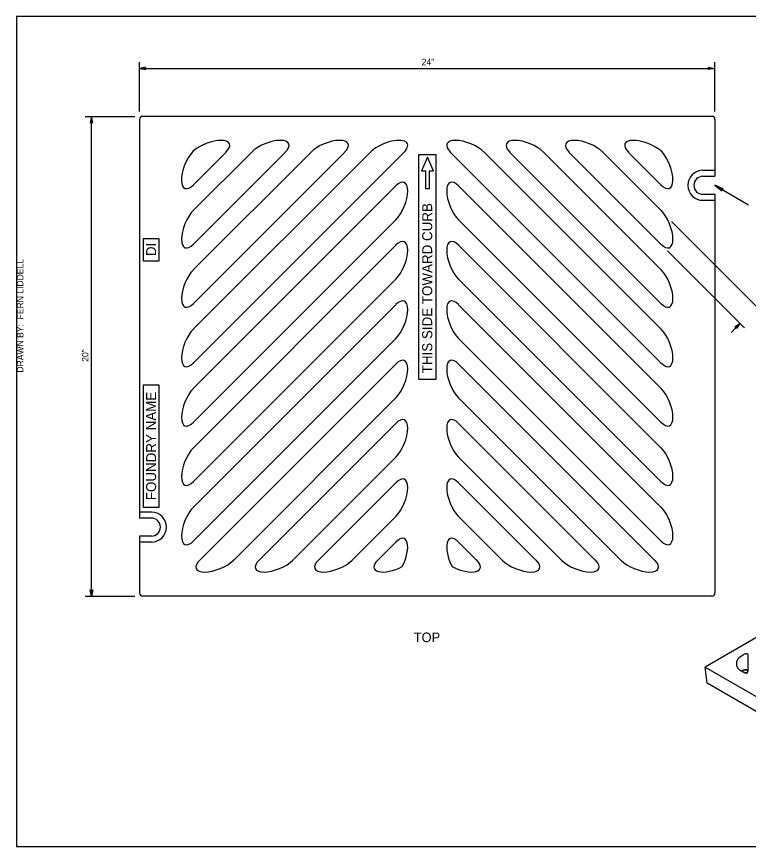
# Model space of a CAD drawing. Extents: x 99862 to 103151, y 100000 to 102076.
# Drawn here: x 99862 to 101693, y 100000 to 102076 of the extents above; entities that cross this region are included whole.
import ezdxf

# ---------------------------------------------------------------- set-up
doc = ezdxf.new("R2010")
doc.units = 0
for name, color, linetype in [('Level 1', 7, 'Continuous'), ('Level 11', 7, 'Continuous'), ('Level 15', 7, 'Continuous'), ('Level 2', 7, 'Continuous'), ('Level 20', 7, 'Continuous'), ('Level 6', 7, 'Continuous'), ('Level 60', 7, 'Continuous'), ('Level 62', 7, 'Continuous')]:
    doc.layers.add(name, color=color, linetype=linetype)

msp = doc.modelspace()

# ---------------------------------------------------------------- linework, layer by layer
at = {"layer": 'Level 1'}
msp.add_lwpolyline([(99862, 99999.5), (103151, 99999.5), (103151, 102075.5), (99862, 102075.5)], close=True, dxfattribs=at)
at = {"layer": 'Level 11'}
for p, q in [((101579.6, 101690.9), (101609.6, 101690.9)), ((101579.6, 101675.9), (101609.6, 101675.9)), ((101579.6, 101630.9), (101609.6, 101630.9)), ((101579.6, 101615.9), (101609.6, 101615.9)), ((100199.6, 100835.9), (100169.6, 100835.9)), ((100199.6, 100820.9), (100169.6, 100820.9)), ((100199.6, 100775.9), (100169.6, 100775.9)), ((100199.6, 100760.9), (100169.6, 100760.9))]:
    msp.add_line(p, q, dxfattribs=at)
for points in [[(100868.3, 101730.7), (100910.9, 101730.7), (100910.9, 101167.3), (100868.3, 101167.3)], [(100178.4, 101464.3), (100218.9, 101464.3), (100218.9, 101519.9), (100178.4, 101519.9)], [(100178.4, 100848.6), (100218.9, 100848.6), (100218.9, 101153.1), (100178.4, 101153.1)]]:
    msp.add_lwpolyline(points, close=True, dxfattribs=at)
msp.add_lwpolyline([(100875.6, 101689.4), (100885.4, 101689.4), (100885.4, 101645.1), (100895.3, 101645.1), (100895.3, 101689.4), (100905.1, 101689.4), (100890.3, 101723.8), (100875.6, 101689.4)], dxfattribs=at)
for centre, radius, start, end in [((101579.6, 101653.4), 37.5, 90, 270), ((101579.6, 101653.4), 22.5, 90, 270), ((100199.6, 100798.4), 37.5, 270, 90), ((100199.6, 100798.4), 22.5, 270, 90)]:
    msp.add_arc(centre, radius, start, end, dxfattribs=at)
at = {"layer": 'Level 15'}
for p, q in [((100169.6, 101837.9), (100169.6, 101961.9)), ((101609.6, 101837.9), (101609.6, 101961.9)), ((100169.6, 101945.9), (101609.6, 101945.9)), ((100033.6, 101825.9), (100157.6, 101825.9)), ((100049.6, 100625.9), (100049.6, 101825.9)), ((101609.1, 101653.5), (101693.4, 101604.8)), ((101501.3, 101563.1), (101725.7, 101338.7)), ((101491.2, 101489.5), (101683.9, 101296.8)), ((101650, 101285.5), (101672.6, 101308.2)), ((100033.6, 100625.9), (100157.6, 100625.9))]:
    msp.add_line(p, q, dxfattribs=at)
for points in [[(100169.6, 101945.9), (100185.3, 101942.8), (100184.6, 101945.9), (100185.3, 101949)], [(101609.6, 101945.9), (101593.9, 101942.8), (101594.6, 101945.9), (101593.9, 101949)], [(100049.6, 101825.9), (100046.5, 101810.2), (100049.6, 101810.9), (100052.7, 101810.2)], [(101609.1, 101653.5), (101627.3, 101639.5), (101627.9, 101642.6), (101630.3, 101644.7)], [(101672.6, 101308.2), (101663.7, 101294.9), (101662, 101297.6), (101659.3, 101299.2)], [(100049.6, 100625.9), (100046.5, 100641.6), (100049.6, 100640.9), (100052.7, 100641.6)]]:
    msp.add_lwpolyline(points, close=True, dxfattribs=at)
at = {"layer": 'Level 2'}
for p, q in [((100169.6, 101818.1), (100169.6, 100820.9)), ((101601.8, 101825.9), (100177.4, 101825.9)), ((101609.6, 101818.1), (101609.6, 101675.9)), ((101609.6, 101630.9), (101609.6, 100633.7)), ((100169.6, 100775.9), (100169.6, 100633.7)), ((101601.8, 100625.9), (100177.4, 100625.9)), ((101584.8, 100448.1), (102009.1, 100203.1))]:
    msp.add_line(p, q, dxfattribs=at)
for points in [[(100304.4, 101590.8), (100304.6, 101591), (100449.5, 101735.9), (100449.5, 101735.9)], [(100304.4, 101442.3), (100304.6, 101442.5), (100598, 101735.9), (100598, 101735.9)], [(100304.4, 101293.9), (100304.6, 101294), (100746.5, 101735.9), (100746.5, 101735.9)], [(100386, 101736), (100385.8, 101735.9), (100304.6, 101654.6), (100304.6, 101654.6)], [(100534.5, 101736), (100534.3, 101735.9), (100304.6, 101506.2), (100304.6, 101506.2)], [(100683, 101736), (100682.8, 101735.9), (100304.6, 101357.7), (100304.6, 101357.7)], [(100831.3, 101735.9), (100831.3, 101735.9), (100304.6, 101209.2), (100304.6, 101209.2)], [(100947.9, 101735.9), (100947.9, 101735.9), (101474.6, 101209.2), (101474.6, 101209.2)], [(101474.8, 101293.9), (101474.6, 101294), (101032.7, 101735.9), (101032.7, 101735.9)], [(101096.2, 101736), (101096.4, 101735.9), (101474.6, 101357.7), (101474.6, 101357.7)], [(101474.8, 101442.3), (101474.6, 101442.5), (101181.2, 101735.9), (101181.2, 101735.9)], [(101244.7, 101736), (101244.9, 101735.9), (101474.6, 101506.2), (101474.6, 101506.2)], [(101474.8, 101590.8), (101474.6, 101591), (101329.7, 101735.9), (101329.7, 101735.9)], [(101393.2, 101736), (101393.4, 101735.9), (101474.6, 101654.6), (101474.6, 101654.6)], [(100304.4, 101145.4), (100304.6, 101145.5), (100810.8, 101651.8), (100810.8, 101651.8)], [(101474.8, 101145.4), (101474.6, 101145.5), (100968.3, 101651.8), (100968.3, 101651.8)], [(100811, 101567.1), (100810.8, 101566.9), (100304.6, 101060.7), (100304.6, 101060.7)], [(100968.2, 101567.1), (100968.3, 101566.9), (101474.6, 101060.7), (101474.6, 101060.7)], [(100304.4, 100996.9), (100304.6, 100997), (100810.8, 101503.3), (100810.8, 101503.3)], [(101474.8, 100996.9), (101474.6, 100997), (100968.3, 101503.3), (100968.3, 101503.3)], [(100811, 101418.6), (100810.8, 101418.4), (100304.6, 100912.2), (100304.6, 100912.2)], [(100968.2, 101418.6), (100968.3, 101418.4), (101474.6, 100912.2), (101474.6, 100912.2)], [(100304.4, 100848.4), (100304.6, 100848.6), (100810.8, 101354.8), (100810.8, 101354.8)], [(101474.8, 100848.4), (101474.6, 100848.6), (100968.3, 101354.8), (100968.3, 101354.8)], [(100811, 101270.1), (100810.8, 101269.9), (100304.6, 100763.7), (100304.6, 100763.7)], [(100968.2, 101270.1), (100968.3, 101269.9), (101474.6, 100763.7), (101474.6, 100763.7)], [(100320.2, 100715.7), (100320.4, 100715.9), (100810.8, 101206.3), (100810.8, 101206.3)], [(101459, 100715.7), (101458.8, 100715.9), (100968.3, 101206.3), (100968.3, 101206.3)], [(100811, 101121.6), (100810.8, 101121.4), (100405.3, 100715.9), (100405.2, 100715.9)], [(100968.2, 101121.6), (100968.3, 101121.4), (101373.9, 100715.9), (101373.9, 100715.9)], [(100468.7, 100715.7), (100468.9, 100715.9), (100810.8, 101057.8), (100810.8, 101057.8)], [(101310.5, 100715.7), (101310.3, 100715.9), (100968.3, 101057.8), (100968.3, 101057.8)], [(100811, 100973.1), (100810.8, 100973), (100553.7, 100715.9), (100553.7, 100715.9)], [(100968.2, 100973.1), (100968.3, 100973), (101225.4, 100715.9), (101225.4, 100715.9)], [(100617.2, 100715.7), (100617.4, 100715.9), (100810.8, 100909.3), (100810.8, 100909.3)], [(101162, 100715.7), (101161.8, 100715.9), (100968.3, 100909.3), (100968.3, 100909.3)], [(100811, 100824.6), (100810.8, 100824.5), (100702.2, 100715.9), (100702.2, 100715.9)], [(100968.2, 100824.6), (100968.3, 100824.5), (101077, 100715.9), (101077, 100715.9)], [(100765.7, 100715.7), (100765.9, 100715.9), (100810.8, 100760.8), (100810.8, 100760.8)], [(101013.5, 100715.7), (101013.3, 100715.9), (100968.3, 100760.8), (100968.3, 100760.8)]]:
    msp.add_lwpolyline(points, dxfattribs=at)
for centre, start, end in [((100177.4, 101818.1), 90, 180), ((101601.8, 101818.1), 0, 90), ((100177.4, 100633.7), 180, 270), ((101601.8, 100633.7), 270, 0)]:
    msp.add_arc(centre, 7.82, start, end, dxfattribs=at)
for centre, major_axis, start_param, end_param in [((100343.4, 101735.9), (51.2, 21.2), 5.503483, 8.580913), ((100491.9, 101735.9), (51.2, 21.2), 5.503483, 8.63938), ((100640.4, 101735.9), (51.2, 21.2), 5.503483, 8.63938), ((100788.9, 101735.9), (51.2, 21.2), 5.497787, 8.63938), ((100990.3, 101735.9), (-51.2, 21.2), 3.926991, 7.068583), ((101138.8, 101735.9), (-51.2, 21.2), 3.926991, 7.062888), ((101287.3, 101735.9), (-51.2, 21.2), 3.926991, 7.062888), ((101435.8, 101735.9), (-51.2, 21.2), 3.985458, 7.062888), ((100304.6, 101697.1), (21.2, 51.2), 0.845165, 3.926991), ((101474.6, 101697.1), (-21.2, 51.2), 2.356194, 5.43802), ((100810.8, 101609.3), (-21.2, -51.2), 0.791094, 3.926991), ((100968.3, 101609.3), (21.2, -51.2), 2.356194, 5.492091), ((100304.6, 101548.6), (21.2, 51.2), 0.791094, 3.926991), ((101474.6, 101548.6), (-21.2, 51.2), 2.356194, 5.492092), ((100810.8, 101460.9), (-21.2, -51.2), 0.791094, 3.926991), ((100968.3, 101460.9), (21.2, -51.2), 2.356194, 5.492092), ((100304.6, 101400.1), (21.2, 51.2), 0.791094, 3.926991), ((101474.6, 101400.1), (-21.2, 51.2), 2.356194, 5.492092), ((100810.8, 101312.4), (-21.2, -51.2), 0.791094, 3.926991), ((100968.3, 101312.4), (21.2, -51.2), 2.356194, 5.492091), ((100304.6, 101251.6), (21.2, 51.2), 0.791094, 3.926991), ((101474.6, 101251.6), (-21.2, 51.2), 2.356194, 5.492091), ((100810.8, 101163.9), (-21.2, -51.2), 0.791094, 3.926991), ((100968.3, 101163.9), (21.2, -51.2), 2.356194, 5.492092), ((100304.6, 101103.1), (21.2, 51.2), 0.791094, 3.926991), ((101474.6, 101103.1), (-21.2, 51.2), 2.356194, 5.492092), ((100810.8, 101015.4), (-21.2, -51.2), 0.791094, 3.926991), ((100968.3, 101015.4), (21.2, -51.2), 2.356194, 5.492091), ((100304.6, 100954.6), (21.2, 51.2), 0.791094, 3.926991), ((101474.6, 100954.6), (-21.2, 51.2), 2.356194, 5.492092), ((100810.8, 100866.9), (-21.2, -51.2), 0.791094, 3.926991), ((100968.3, 100866.9), (21.2, -51.2), 2.356194, 5.492091), ((100304.6, 100806.1), (21.2, 51.2), 0.791094, 3.926991), ((101474.6, 100806.1), (-21.2, 51.2), 2.356194, 5.492091), ((100810.8, 100718.4), (-21.2, -51.2), 1.366386, 3.926991), ((100968.3, 100718.4), (21.2, -51.2), 2.356194, 4.9168), ((100362.8, 100715.9), (51.2, 21.2), 2.36189, 5.497787), ((100511.3, 100715.9), (51.2, 21.2), 2.36189, 5.497787), ((100659.8, 100715.9), (51.2, 21.2), 2.36189, 5.497787), ((100808.3, 100715.9), (51.2, 21.2), 2.36189, 4.916904), ((100970.9, 100715.9), (-51.2, 21.2), 1.366282, 3.921295), ((101119.4, 100715.9), (-51.2, 21.2), 0.785398, 3.921295), ((101267.9, 100715.9), (-51.2, 21.2), 0.785398, 3.921295), ((101416.4, 100715.9), (-51.2, 21.2), 0.785398, 3.921295)]:
    msp.add_ellipse(centre, major_axis=major_axis, ratio=0.414214, start_param=start_param, end_param=end_param, dxfattribs=at)
for points in [[(101693.1, 100473.9), (101693.1, 100457.3), (101693.1, 100440.7), (101693.1, 100428.8), (101678.5, 100436.8), (101664, 100444.9), (101663.1, 100457.2), (101664, 100469.6), (101678.5, 100477.6), (101693, 100485.7), (101693.1, 100473.9)], [(101693, 100439.2), (101688.3, 100444.1), (101678.2, 100439.1), (101677.3, 100438.6), (101676.5, 100438.1)], [(101676.5, 100438.1), (101677.3, 100438.6), (101678.2, 100439.1), (101688.3, 100444.1), (101693, 100439.2)], [(101676.5, 100438.1), (101677.5, 100437.4), (101678.5, 100436.8), (101691.3, 100429.8), (101693, 100439.2)]]:
    msp.add_open_spline(points, degree=4, dxfattribs=at)
at = {"layer": 'Level 6'}
for points in [[(102518.2, 100497.1), (102518.2, 100497.1), (102093.9, 100742), (101584.8, 100448.1)], [(102009.1, 100166.4), (102009.1, 100166.4), (101590.1, 100408.3), (101584.8, 100448.1)]]:
    msp.add_lwpolyline(points, dxfattribs=at)
at = {"layer": 'Level 60'}
msp.add_line((99862, 99999.5), (99862, 99999.5), dxfattribs=at)

# ---------------------------------------------------------------- texts
at = {"layer": 'Level 11'}
for s, height, p in [('THIS SIDE TOWARD CURB', 25.028, (100902.1, 101183.1)), ('DI', 25.03, (100211.1, 101476.2)), ('FOUNDRY NAME', 25.028, (100211.1, 100865.6))]:
    msp.add_text(s, height=height, rotation=90, dxfattribs=at).set_placement(p)
at = {"layer": 'Level 20'}
for s, height, p in [('24"', 16, (100875.7, 101953.9)), ('TOP', 24, (100856, 100510.6))]:
    msp.add_text(s, height=height, dxfattribs=at).set_placement(p)
msp.add_text('20"', height=16, rotation=90, dxfattribs=at).set_placement((100041.6, 101212))
at = {"layer": 'Level 62'}
msp.add_text('DRAWN BY:  FERN LIDDELL', height=16, rotation=90, dxfattribs=at).set_placement((99879, 101184.9))

doc.saveas('drawing.dxf')
